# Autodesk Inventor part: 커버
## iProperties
Company: 한국ATC센터
Created: 2014-10
Part Number: 커버
Document SubType Name: Modeling
Designer: KYOUNG IL JANG
Density: 1 g/cm^3
Mass: 44.7286 g
Surface Area: 161.165 cm^2
Volume: 44.7286 cm^3
Author: KYOUNG IL JANG
Revision Number: 1
